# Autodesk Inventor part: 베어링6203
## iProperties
IsCustomPart: 0
Company: 한국ATC센터
Created: 2014-12
Part Number: 베어링6203
Material: 강, 연강
Description: 깊은 그루브 볼 베어링
Document SubType Name: Modeling
Standard: KS B 2023
Designer: KYOUNG IL JANG
Standards Organization: KS
Language: ko-KR
Size Designation: 6203 - 17 x 40 x 12
Categories: <MemberInstance><Categories><Category DisplayName="샤프트 부품" InternalName="7f7aeb1f-a693-4053-b835-cee3144e0d98" Mnemonic="SHFT"><Category DisplayName="베어링" Inter
Density: 7.86 g/cm^3
Mass: 64.9809 g
Surface Area: 64.3582 cm^2
Volume: 8.26729 cm^3
Author: KYOUNG IL JANG
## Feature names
1. IDS_ARRAYBALL[SIMPL:T] [Circular Pattern]
